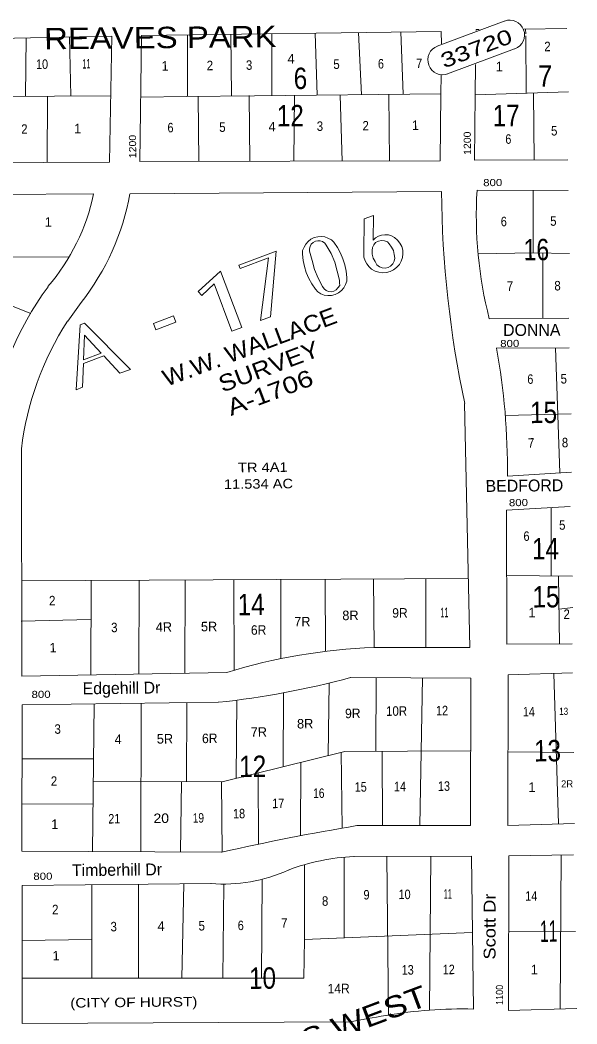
# Model space of a CAD drawing. Extents: x 2356373 to 2371954, y 6966197 to 6989612.
# Drawn here: x 2370920 to 2371856, y 6987237 to 6988926 of the extents above; entities that cross this region are included whole.
import ezdxf

# ---------------------------------------------------------------- set-up
doc = ezdxf.new("R2010")
doc.units = 0
doc.header["$LTSCALE"] = 6.4
doc.linetypes.add('DOTTED', pattern=[1.5, 0.3, -1.2])
for name, color, linetype in [('10', 7, 'Continuous'), ('11', 7, 'Continuous'), ('18', 7, 'Continuous'), ('20', 7, 'Continuous'), ('22', 7, 'Continuous'), ('24', 7, 'Continuous')]:
    doc.layers.add(name, color=color, linetype=linetype)
for name, color, linetype, lineweight in [('12', 7, 'Continuous', 13), ('15', 7, 'Continuous', 13), ('16', 7, 'DOTTED', 13), ('17', 7, 'Continuous', 13), ('19', 7, 'Continuous', 13), ('6', 7, 'DOTTED', 13)]:
    doc.layers.add(name, color=color, linetype=linetype, lineweight=lineweight)

msp = doc.modelspace()

# ---------------------------------------------------------------- linework, layer by layer
at = {"layer": '15'}
for p, q in [((2371074.591, 6988898.515), (2370862.686, 6988894.533)), ((2371628.363, 6988906.653), (2371628.567, 6988885.961)), ((2371839.261, 6988911.325), (2371767.289, 6988910.617)), ((2371628.088, 6988832.87), (2371627.398, 6988801.473)), ((2371627.398, 6988801.473), (2371626.505, 6988688.794)), ((2371684.479, 6988689.862), (2371841.431, 6988690.404)), ((2371044.203, 6988633.587), (2370746.301, 6988631.662)), ((2371105.19, 6988633.288), (2371628.008, 6988637.623)), ((2371841.933, 6988639.223), (2371688.972, 6988639.521)), ((2371000.321, 6988419.013), (2371023.003, 6988450.828)), ((2371710.091, 6988423.185), (2371843.043, 6988424.491)), ((2371843.539, 6988374.11), (2371720.575, 6988373.701)), ((2371739.685, 6988158.347), (2371847.591, 6988165.106)), ((2371678.043, 6987818.332), (2371476.083, 6987819.648)), ((2371678.985, 6987518.821), (2371482.041, 6987518.586)), ((2371678.985, 6987518.821), (2371682.51, 6987261.825))]:
    msp.add_line(p, q, dxfattribs=at)
for points in [[(2371074.591, 6988898.515), (2371070.671, 6988686.934), (2370065.993, 6988681.563), (2370066.916, 6988791.144), (2370017.925, 6988791.462), (2370017.998, 6988682.191), (2369959.999, 6988683.621)], [(2371626.505, 6988688.794), (2371121.65, 6988687.633), (2371124.562, 6988900.105), (2371628.363, 6988906.653)], [(2371692.314, 6988909.981), (2371687.316, 6988909.932), (2371687.335, 6988908.033)], [(2371685.896, 6988850.934), (2371685.397, 6988800.042), (2371684.479, 6988689.862)], [(2371667.505, 6988280.506), (2371676.534, 6987870.103), (2371515.577, 6987870.122)], [(2371268.055, 6987828.202), (2370923.21, 6987821.814), (2370922.451, 6988204.406)], [(2371845.16, 6988107.098), (2371738.247, 6988101.348), (2371738.463, 6987875.61), (2371848.427, 6987876.391)], [(2371678.043, 6987818.332), (2371677.479, 6987570.393), (2371486.53, 6987570.416)], [(2371848.908, 6987827.408), (2371740.969, 6987824.249), (2371740.457, 6987570.812), (2371852.398, 6987573.91)], [(2371253.554, 6987777.873), (2370923.681, 6987773.833), (2370923.105, 6987527.192), (2371259.028, 6987525.893)], [(2371850.914, 6987521.309), (2371741.962, 6987519.441), (2371741.52, 6987259.106), (2371856.454, 6987262.733)], [(2371241.553, 6987472.935), (2370923.67, 6987469.614), (2370923.949, 6987237.678), (2371474.775, 6987240.39)]]:
    msp.add_lwpolyline(points, dxfattribs=at)
for centre, radius, start, end in [((2370702.598, 6988704.412), 348.55, 319.32276, 348.28276), ((2370702.598, 6988704.412), 408.531, 321.63276, 349.98276), ((2373454.332, 6988656.66), 1825.725, 180.60276, 191.89276), ((2372385.206, 6988596.772), 697.93, 176.49276, 194.40276), ((2371425.913, 6988143.768), 567.011, 143.99276, 170.82276), ((2371425.913, 6988143.768), 507.03, 147.13276, 173.13276), ((2370602.879, 6988169.575), 1136.842, 359.43276, 10.34276), ((2371552.101, 6986899.84), 970.974, 92.19476, 107.03276), ((2371106.902, 6989171.36), 1401.158, 276.01276, 285.26276), ((2372161.01, 6983533.721), 4092.61, 99.48376, 102.72276), ((2371500.654, 6987150.268), 368.824, 92.98776, 110.53276), ((2371261.949, 6987737.466), 265.346, 265.44276, 294.32276), ((2371665.024, 6986497.457), 764.549, 88.70376, 99.75376), ((2380526.185, 6935044.151), 52975.304, 99.77176, 99.83876)]:
    msp.add_arc(centre, radius, start, end, dxfattribs=at)
at = {"layer": '16', "linetype": 'Continuous'}
for p, q in [((2371072.574, 6988798.522), (2370450.786, 6988793.914)), ((2371123.582, 6988796.323), (2371199.555, 6988797.069)), ((2371199.555, 6988797.069), (2371314.511, 6988798.298)), ((2371314.511, 6988798.298), (2371627.398, 6988801.473)), ((2371685.397, 6988800.042), (2371842.308, 6988804.783)), ((2371735.686, 6988260.28), (2371846.625, 6988263.37)), ((2370922.633, 6987982.366), (2371674.392, 6987986.452))]:
    msp.add_line(p, q, dxfattribs=at)
at = {"layer": '17'}
for p, q in [((2371621.606, 6988882.093), (2371734.163, 6988924.188)), ((2371639.062, 6988835.278), (2371751.618, 6988877.472))]:
    msp.add_line(p, q, dxfattribs=at)
for points in [[(2371513.842, 6988555.722), (2371514.435, 6988597.218), (2371498.498, 6988591.163), (2371498.071, 6988532.874), (2371498.13, 6988526.775), (2371500.187, 6988520.897), (2371503.241, 6988515.529), (2371507.286, 6988510.669), (2371511.326, 6988506.611), (2371517.354, 6988503.57), (2371523.373, 6988501.43), (2371529.38, 6988500.59), (2371536.373, 6988500.958), (2371542.356, 6988502.617), (2371548.327, 6988505.474), (2371553.286, 6988509.521), (2371558.236, 6988514.369), (2371561.18, 6988520.096), (2371563.12, 6988526.115), (2371564.059, 6988532.322), (2371563.996, 6988538.719), (2371561.935, 6988544.898), (2371558.88, 6988550.566), (2371554.833, 6988555.525), (2371549.793, 6988559.673), (2371544.764, 6988562.724), (2371539.752, 6988564.175), (2371533.75, 6988564.516), (2371527.758, 6988563.858), (2371522.776, 6988562.108), (2371517.806, 6988559.361), (2371513.842, 6988555.722)], [(2371437.832, 6988558.875), (2371432.813, 6988560.824), (2371426.807, 6988561.666), (2371420.812, 6988561.306), (2371414.828, 6988559.748), (2371408.856, 6988557.09), (2371404.895, 6988553.352), (2371400.94, 6988548.814), (2371397.992, 6988543.587), (2371395.049, 6988537.861), (2371395.108, 6988531.962), (2371396.211, 6988521.375), (2371398.312, 6988510.999), (2371401.41, 6988500.932), (2371405.505, 6988491.076), (2371410.596, 6988481.727), (2371416.682, 6988472.89), (2371420.723, 6988468.631), (2371425.754, 6988465.281), (2371431.773, 6988463.14), (2371437.781, 6988462.2), (2371443.776, 6988462.559), (2371449.759, 6988464.117), (2371455.73, 6988466.874), (2371460.692, 6988470.622), (2371464.645, 6988475.36), (2371467.591, 6988480.788), (2371469.532, 6988486.706), (2371469.471, 6988492.902), (2371468.368, 6988503.39), (2371466.268, 6988513.765), (2371463.169, 6988523.933), (2371459.073, 6988533.691), (2371453.983, 6988543.037), (2371447.898, 6988551.875), (2371443.859, 6988555.936), (2371437.832, 6988558.875)], [(2371409.939, 6988548.704), (2371412.909, 6988551.732), (2371416.887, 6988553.77), (2371420.878, 6988554.608), (2371424.878, 6988554.348), (2371428.892, 6988552.989), (2371432.916, 6988550.428), (2371434.948, 6988547.05), (2371443.082, 6988533.132), (2371449.224, 6988518.596), (2371453.371, 6988503.542), (2371457.522, 6988488.186), (2371457.566, 6988483.588), (2371457.61, 6988479.09), (2371454.65, 6988475.062), (2371451.685, 6988471.634), (2371447.707, 6988469.395), (2371443.718, 6988468.456), (2371438.714, 6988469.007), (2371434.697, 6988470.767), (2371431.67, 6988473.737), (2371428.632, 6988477.607), (2371421.495, 6988491.632), (2371415.355, 6988506.168), (2371411.209, 6988521.223), (2371407.057, 6988536.677), (2371407.016, 6988540.877), (2371407.976, 6988544.985), (2371409.939, 6988548.704)], [(2371517.881, 6988551.563), (2371514.919, 6988547.835), (2371512.965, 6988543.217), (2371512.015, 6988538.209), (2371512.078, 6988531.711), (2371514.139, 6988525.433), (2371517.198, 6988519.465), (2371520.25, 6988513.997), (2371524.28, 6988510.837), (2371529.299, 6988508.787), (2371534.302, 6988508.336), (2371539.29, 6988509.385), (2371543.264, 6988511.923), (2371547.226, 6988515.661), (2371549.181, 6988520.178), (2371550.132, 6988525.186), (2371549.071, 6988531.574), (2371548.009, 6988537.862), (2371544.95, 6988543.831), (2371540.897, 6988549.29), (2371537.865, 6988552.659), (2371532.849, 6988554.608), (2371527.845, 6988555.06), (2371522.856, 6988554.011), (2371517.881, 6988551.563)], [(2371338.182, 6988525.904), (2371290.371, 6988507.939), (2371288.319, 6988513.217), (2371351.071, 6988536.928), (2371341.16, 6988426.259), (2371324.224, 6988420.196), (2371338.182, 6988525.904)], [(2371225.836, 6988462.317), (2371246.635, 6988482.216), (2371276.414, 6988402.13), (2371293.349, 6988408.295), (2371257.428, 6988503.117), (2371219.772, 6988469.057), (2371225.836, 6988462.317)], [(2371182.287, 6988417.601), (2371148.423, 6988404.673), (2371144.319, 6988415.429), (2371178.183, 6988428.358), (2371182.287, 6988417.601)], [(2371106.09, 6988338.073), (2371028.346, 6988415.789), (2371021.373, 6988413.221), (2371014.451, 6988303.683), (2371025.407, 6988307.889), (2371027.012, 6988348.094), (2371060.876, 6988360.925), (2371088.158, 6988331.6), (2371106.09, 6988338.073)], [(2371028.547, 6988395.397), (2371056.834, 6988365.482), (2371026.951, 6988354.292), (2371028.547, 6988395.397)]]:
    msp.add_lwpolyline(points, close=True, dxfattribs=at)
for centre, start, end in [((2371743.39, 6988900.785), 290.56276, 110.56276), ((2371630.834, 6988858.691), 110.56276, 290.56276)]:
    msp.add_arc(centre, 24.992, start, end, dxfattribs=at)
at = {"layer": '6', "linetype": 'Continuous'}
for p, q in [((2370930.655, 6988895.802), (2370929.621, 6988797.517)), ((2371003.623, 6988897.218), (2371005.598, 6988798.064)), ((2371201.531, 6988901.162), (2371201.546, 6988797.989)), ((2371274.504, 6988902.078), (2371275.525, 6988797.916)), ((2371343.476, 6988902.955), (2371343.502, 6988798.584)), ((2371416.446, 6988903.973), (2371419.474, 6988799.33)), ((2371489.418, 6988904.889), (2371494.445, 6988800.166)), ((2371564.42, 6988800.853), (2371560.39, 6988905.786)), ((2371770.286, 6988910.647), (2371770.366, 6988902.55)), ((2371770.399, 6988899.251), (2371771.348, 6988802.586)), ((2370966.609, 6988797.781), (2370965.704, 6988686.402)), ((2371220.623, 6988687.806), (2371219.547, 6988797.266)), ((2371306.598, 6988688.049), (2371305.508, 6988798.909)), ((2371381.487, 6988798.956), (2371380.575, 6988688.177)), ((2371458.46, 6988799.713), (2371461.553, 6988688.373)), ((2371540.429, 6988800.618), (2371541.529, 6988688.559)), ((2371783.34, 6988803.004), (2371784.448, 6988690.246)), ((2370728.346, 6988525.813), (2371003.258, 6988527.213)), ((2371691.025, 6988532.27), (2371782.981, 6988534.371)), ((2371798.978, 6988534.028), (2371799.059, 6988424.06)), ((2370938.209, 6988432.199), (2370813.765, 6988480.864)), ((2371820.544, 6988374.084), (2371827.61, 6988163.809)), ((2371813.316, 6987990.414), (2371813.187, 6988105.383)), ((2371039.595, 6987983.016), (2371039.158, 6987823.954)), ((2371120.57, 6987983.411), (2371120.122, 6987825.45)), ((2371197.546, 6987983.867), (2371197.087, 6987826.904)), ((2371279.519, 6987984.272), (2371280.018, 6987831.719)), ((2371358.494, 6987984.748), (2371358.805, 6987851.187)), ((2371433.47, 6987985.185), (2371433.665, 6987863.52)), ((2371514.443, 6987985.58), (2371515.577, 6987870.122)), ((2371602.416, 6987986.044), (2371602.554, 6987870.077)), ((2371738.326, 6987991.378), (2371849.311, 6987989.969)), ((2371827.434, 6987876.284), (2371825.315, 6987990.232)), ((2371826.863, 6987934.364), (2371849.828, 6987937.389)), ((2370922.301, 6987914.382), (2371039.243, 6987917.229)), ((2371519.076, 6987819.37), (2371518.293, 6987695.395)), ((2371597.06, 6987818.837), (2371592.502, 6987570.458)), ((2371817.926, 6987826.505), (2371825.412, 6987573.146)), ((2371440.186, 6987810.198), (2371438.383, 6987688.412)), ((2371284.51, 6987781.476), (2371283.801, 6987650.204)), ((2371363.367, 6987793.847), (2371362.587, 6987669.772)), ((2371044.635, 6987775.32), (2371042.078, 6987526.762)), ((2371123.604, 6987776.297), (2371123.06, 6987526.358)), ((2371200.575, 6987777.252), (2371199.879, 6987644.381)), ((2370923.577, 6987682.755), (2371043.547, 6987682.534)), ((2371460.325, 6987693.726), (2371461.579, 6987566.173)), ((2371529.289, 6987695.504), (2371529.517, 6987570.438)), ((2371740.24, 6987694.776), (2371851.226, 6987693.266)), ((2371392.508, 6987676.965), (2371391.723, 6987553.39)), ((2371320.702, 6987659.164), (2371320.88, 6987539.298)), ((2371191.881, 6987644.402), (2371190.044, 6987526.115)), ((2371258.863, 6987644.261), (2371260.027, 6987526.003)), ((2370923.319, 6987607.174), (2371043.295, 6987606.353)), ((2371465.056, 6987517.32), (2371465.388, 6987381.76)), ((2371537.025, 6987518.626), (2371539.647, 6987251.724)), ((2371611.005, 6987518.753), (2371608.548, 6987259.898)), ((2371829.924, 6987521.003), (2371828.472, 6987261.759)), ((2371398.201, 6987504.466), (2371398.434, 6987378.903)), ((2371327.459, 6987480.177), (2371326.095, 6987313.71)), ((2371040.626, 6987470.862), (2371041.169, 6987313.809)), ((2371119.598, 6987471.637), (2371119.15, 6987313.776)), ((2371195.569, 6987472.484), (2371192.13, 6987313.793)), ((2371262.557, 6987472.044), (2371261.111, 6987313.771)), ((2371742.22, 6987391.477), (2371854.182, 6987392.176)), ((2370923.578, 6987377.237), (2371040.532, 6987378.686))]:
    msp.add_line(p, q, dxfattribs=at)
for points in [[(2371782.949, 6988639.344), (2371782.981, 6988534.371), (2371843.979, 6988532.872)], [(2371042.919, 6987644.738), (2371259.865, 6987644.171), (2371466.31, 6987695.184), (2371677.244, 6987696.157)], [(2370924.202, 6987313.861), (2371397.077, 6987313.706), (2371398.434, 6987378.903), (2371680.243, 6987390.768)]]:
    msp.add_lwpolyline(points, dxfattribs=at)

# ---------------------------------------------------------------- texts
at = {"layer": '10', "width": 1.15}
msp.add_text('TR 4A1', height=15.99, rotation=0.563, dxfattribs=at).set_placement((2371286.743, 6988164.895))
at = {"layer": '11', "width": 1.15}
msp.add_text('11.534 AC', height=15.99, rotation=0.563, dxfattribs=at).set_placement((2371263.025, 6988136.87))
at = {"layer": '12'}
for s, height, width, p in [('2', 15.99, 0.9, (2371801.644, 6988873.365)), ('10', 15.99, 0.85, (2370947.167, 6988843.479)), ('11', 15.99, 0.55, (2371025.138, 6988844.244)), ('2', 15.99, 0.9, (2371234.11, 6988841.397)), ('3', 15.99, 0.9, (2371300.086, 6988842.045)), ('5', 15.99, 0.9, (2371447.033, 6988843.489)), ('6', 15.99, 0.85, (2371522.006, 6988844.225)), ('7', 15.99, 0.9, (2371585.983, 6988844.855)), ('2', 15.99, 0.9, (2370922.245, 6988734.362)), ('6', 15.99, 0.85, (2371168.155, 6988736.777)), ('5', 15.99, 0.9, (2371255.123, 6988737.632)), ('3', 15.99, 0.9, (2371419.065, 6988739.242)), ('2', 15.99, 0.9, (2371496.036, 6988739.999)), ('5', 15.99, 0.9, (2371813.035, 6988731.515)), ('6', 15.99, 0.85, (2371736.193, 6988717.564)), ('6', 15.99, 0.85, (2371728.558, 6988578.825)), ('5', 15.99, 0.9, (2371811.527, 6988579.641)), ('7', 15.99, 0.9, (2371738.624, 6988470.053)), ('8', 15.99, 0.9, (2371818.594, 6988470.838)), ('6', 15.99, 0.85, (2371773.152, 6988313.634)), ('5', 15.99, 0.9, (2371829.132, 6988314.185)), ('7', 15.99, 0.9, (2371774.206, 6988206.273)), ('8', 15.99, 0.9, (2371831.184, 6988206.833)), ('5', 15.99, 0.9, (2371826.548, 6988068.225)), ('6', 15.99, 0.85, (2371766.749, 6988049.443)), ('2', 15.99, 0.9, (2370969.028, 6987940.933)), ('9R', 15.99, 0.95, (2371546.077, 6987920.208)), ('11', 15.99, 0.55, (2371627.048, 6987921.003)), ('2', 15.99, 0.9, (2371834.02, 6987918.139)), ('3', 15.99, 0.9, (2371073.443, 6987895.771)), ('6R', 15.99, 0.95, (2371308.423, 6987891.481)), ('9R', 15.99, 0.95, (2371466.76, 6987751.075)), ('10R', 15.99, 0.9, (2371535.702, 6987755.05)), ('12', 15.99, 0.85, (2371619.673, 6987755.876)), ('14', 15.99, 0.85, (2371765.651, 6987754.01)), ('13', 12, 0.85, (2371826.61, 6987756.608)), ('3', 15.99, 0.9, (2370978.148, 6987724.88)), ('6R', 15.99, 0.95, (2371226.237, 6987709.122)), ('2', 15.99, 0.9, (2370972.01, 6987637.344)), ('13', 15.99, 0.85, (2371622.919, 6987628.841)), ('16', 15.99, 0.8, (2371413.093, 6987616.882)), ('15', 15.99, 0.85, (2371482.971, 6987627.467)), ('14', 15.99, 0.85, (2371548.946, 6987628.114)), ('17', 15.99, 0.85, (2371344.279, 6987599.712)), ('18', 15.99, 0.85, (2371278.466, 6987582.568)), ('21', 15.99, 0.85, (2371068.606, 6987573.909)), ('20', 15.99, 1.1, (2371144.58, 6987574.656)), ('19', 15.99, 0.8, (2371210.556, 6987575.303)), ('9', 15.99, 0.85, (2371497.75, 6987446.061)), ('10', 15.99, 0.85, (2371556.726, 6987446.639)), ('11', 15.99, 0.55, (2371632.7, 6987447.386)), ('14', 15.99, 0.85, (2371769.699, 6987443.833)), ('8', 15.99, 0.9, (2371427.871, 6987435.476)), ('2', 15.99, 0.9, (2370974.134, 6987421.122)), ('5', 15.99, 0.9, (2371220.336, 6987393.847)), ('6', 15.99, 0.85, (2371286.312, 6987394.497)), ('7', 15.99, 0.9, (2371359.254, 6987398.512)), ('3', 15.99, 0.9, (2371072.389, 6987392.395)), ('13', 15.99, 0.85, (2371561.974, 6987319.624)), ('12', 15.99, 0.85, (2371630.949, 6987320.302)), ('14R', 15.99, 0.95, (2371437.317, 6987288.108)), ('(CITY OF HURST)', 15.99, 1.2, (2371004.666, 6987264.164))]:
    msp.add_text(s, height=height, rotation=0.563, dxfattribs=dict(at, width=width)).set_placement(p)
for s, height, p in [('4', 15.99, (2371369.964, 6988852.63)), ('1', 15.99, (2371158.137, 6988840.652)), ('1', 15.99, (2371719.999, 6988839.571)), ('1', 15.99, (2371011.212, 6988735.236)), ('4', 15.99, (2371338.094, 6988738.447)), ('1', 15.99, (2371579.005, 6988740.813)), ('1', 15.99, (2370961.771, 6988577.892)), ('8R', 15.99, (2371462.14, 6987916.085)), ('1', 15.99, (2371775.011, 6987920.857)), ('7R', 15.99, (2371381.267, 6987905.393)), ('4R', 15.99, (2371148.416, 6987896.507)), ('5R', 15.99, (2371224.39, 6987897.254)), ('1', 15.99, (2370969.805, 6987861.762)), ('8R', 15.99, (2371385.952, 6987733.786)), ('7R', 15.99, (2371308.109, 6987719.824)), ('4', 15.99, (2371079.291, 6987707.68)), ('5R', 15.99, (2371150.264, 6987708.377)), ('2R', 12, (2371829.808, 6987634.573)), ('1', 15.99, (2371774.897, 6987627.035)), ('1', 15.99, (2370972.723, 6987564.67)), ('4', 15.99, (2371151.361, 6987393.171)), ('1', 15.99, (2370974.896, 6987343.55)), ('1', 15.99, (2371778.911, 6987320.157))]:
    msp.add_text(s, height=height, rotation=0.563, dxfattribs=at).set_placement(p)
at = {"layer": '17', "width": 1.35}
msp.add_text('33720', height=24.99, rotation=20.563, dxfattribs=at).set_placement((2371632.975, 6988844.315))
at = {"layer": '18'}
for s, rotation, width, p in [('REAVES PARK', 0.563, 1.15, (2370960.839, 6988876.504)), ('FOREST OAKS WEST', 20.563, 1.2, (2371052.657, 6987060.291))]:
    msp.add_text(s, height=35.99, rotation=rotation, dxfattribs=dict(at, width=width)).set_placement(p)
at = {"layer": '19'}
for s, rotation, p in [('DONNA', 0.203, (2371732.371, 6988394.212)), ('BEDFORD', 0.563, (2371702.956, 6988131.893)), ('Edgehill Dr', 0.7, (2371025.483, 6987791.229)), ('Timberhill Dr', 0.603, (2371007.494, 6987485.333))]:
    msp.add_text(s, height=19.99, rotation=rotation, dxfattribs=at).set_placement(p)
at = {"layer": '19', "width": 1.15}
msp.add_text('Scott Dr', height=19.99, rotation=90.039, dxfattribs=at).set_placement((2371719.681, 6987345.068))
at = {"layer": '20'}
for s, width, p in [('W.W. WALLACE', 1.1, (2371166.362, 6988308.674)), ('SURVEY', 1.15, (2371260.434, 6988298.801)), ('A-1706', 1.25, (2371274.816, 6988259.553))]:
    msp.add_text(s, height=27.99, rotation=20.563, dxfattribs=dict(at, width=width)).set_placement(p)
at = {"layer": '22'}
for s, width, p in [('6', 0.85, (2371380.383, 6988809.644)), ('7', 0.9, (2371791.234, 6988813.678)), ('12', 0.85, (2371352.009, 6988746.681)), ('17', 0.85, (2371714.911, 6988746.946)), ('16', 0.8, (2371767.11, 6988521.419)), ('15', 0.85, (2371777.8, 6988247.498)), ('14', 0.85, (2371781.051, 6988018.191)), ('15', 0.85, (2371781.846, 6987937.32)), ('14', 0.85, (2371286.108, 6987924.153)), ('13', 0.85, (2371784.391, 6987678.214)), ('12', 0.85, (2371288.782, 6987651.851)), ('11', 0.55, (2371794.371, 6987374.693)), ('10', 0.85, (2371305.279, 6987295.609))]:
    msp.add_text(s, height=35.99, rotation=0.563, dxfattribs=dict(at, width=width)).set_placement(p)
at = {"layer": '24'}
for s, rotation, width, p in [('1200', 90.563, 1.1, (2371115.595, 6988693.472)), ('1200', 90.563, 1.1, (2371678.39, 6988699)), ('800', 0.563, 1.2, (2371698.903, 6988646.215)), ('800', 0.563, 1.2, (2371727.557, 6988375.47)), ('800', 0.563, 1.2, (2371742.181, 6988107.784)), ('800', 0.563, 1.2, (2370939.568, 6987785.085)), ('800', 0.563, 1.2, (2370942.572, 6987479.096)), ('1100', 90.563, 0.95, (2371732.429, 6987268.712))]:
    msp.add_text(s, height=12, rotation=rotation, dxfattribs=dict(at, width=width)).set_placement(p)

doc.saveas('drawing.dxf')
